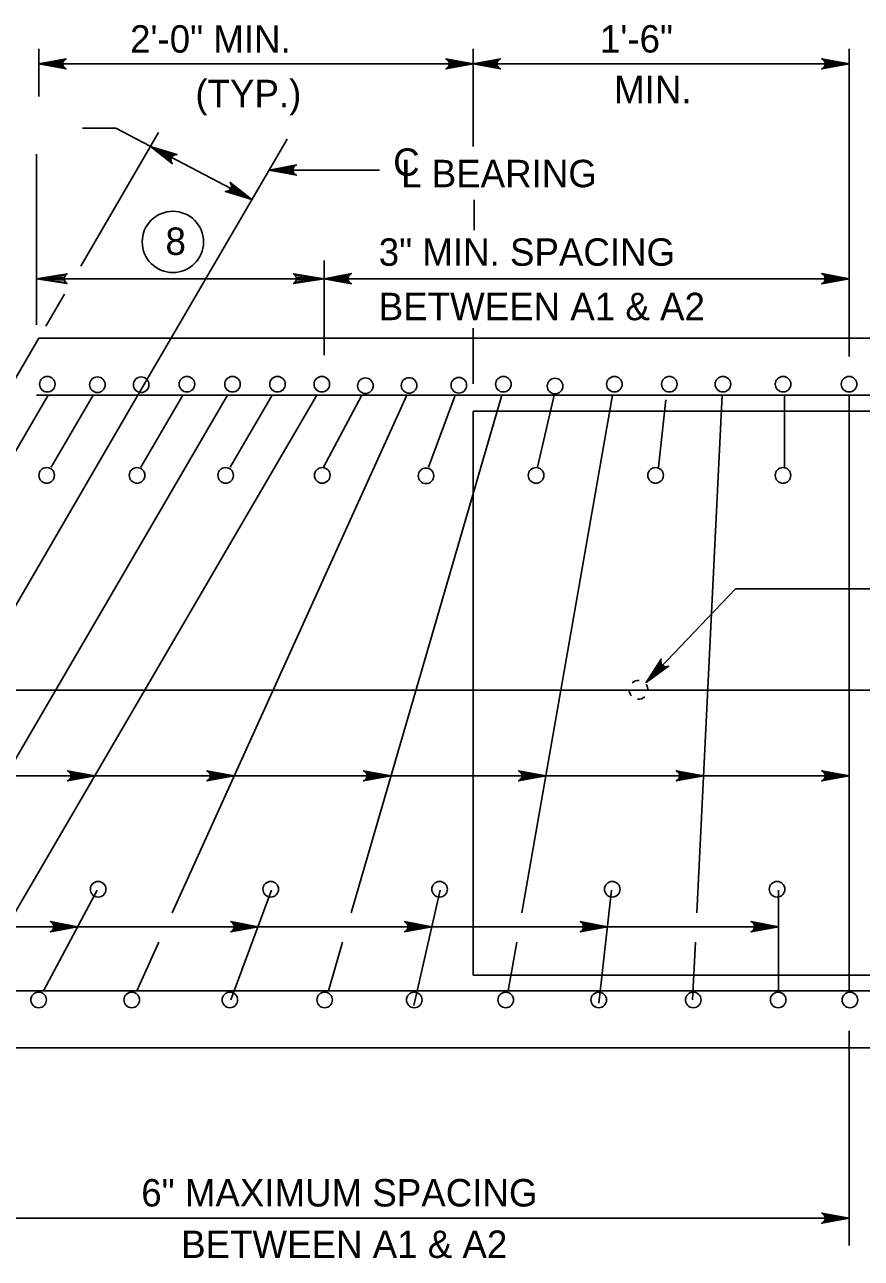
# Model space of a CAD drawing. Extents: x 639331 to 643089, y 299088 to 300975.
# Drawn here: x 641717.4 to 641808.9, y 299343 to 299477.9 of the extents above; entities that cross this region are included whole.
import ezdxf

# ---------------------------------------------------------------- set-up
doc = ezdxf.new("R2010")
doc.units = 0
doc.layers.add('1', color=7, linetype='Continuous')

msp = doc.modelspace()

# ---------------------------------------------------------------- linework, layer by layer
at = {"layer": '1'}
for p, q in [((641718.94, 299473.67), (641766.44, 299473.67)), ((641766.44, 299473.67), (641807.54, 299473.67)), ((641723.54, 299451.55), (641732.02, 299466.16)), ((641727.35, 299466.62), (641723.72, 299466.62)), ((641742.25, 299458.83), (641727.35, 299466.62)), ((641729.52, 299437), (641746.1, 299465.44)), ((641756.19, 299462.05), (641744.13, 299462.05)), ((641750.14, 299450.17), (641718.69, 299450.17)), ((641807.54, 299450.17), (641750.14, 299450.17)), ((641719.71, 299444.96), (641721.75, 299448.47)), ((641673.69, 299366.05), (641718.94, 299443.67)), ((641824.06, 299443.67), (641718.94, 299443.67)), ((641686.95, 299380.81), (641719.95, 299437.42)), ((641696.77, 299380.81), (641729.77, 299437.42)), ((641706.56, 299380.81), (641739.56, 299437.42)), ((641716.33, 299380.81), (641749.33, 299437.42)), ((641824.06, 299437.42), (641718.68, 299437.42)), ((641720.29, 299429.55), (641724.88, 299437.42)), ((641730.08, 299429.55), (641734.67, 299437.42)), ((641733.51, 299380.81), (641759.19, 299437.42)), ((641739.85, 299429.55), (641744.44, 299437.42)), ((641750.07, 299429.55), (641754.28, 299437.42)), ((641753.08, 299380.81), (641769.56, 299437.42)), ((641761.56, 299429.55), (641764.45, 299437.33)), ((641771.77, 299380.81), (641781.66, 299437.42)), ((641773.47, 299429.55), (641775.28, 299437.42)), ((641786.7, 299429.55), (641787.52, 299436.92)), ((641790.9, 299380.81), (641793.66, 299437.42)), ((641800.49, 299429.55), (641800.49, 299437.42)), ((641807.54, 299372.3), (641807.54, 299437.42)), ((641766.44, 299435.67), (641766.44, 299374)), ((641824.31, 299435.67), (641766.44, 299435.67)), ((641785.34, 299406.01), (641795.11, 299416.26)), ((641795.11, 299416.26), (641829.93, 299416.26)), ((641844.19, 299405.17), (641682.94, 299405.17)), ((641725.07, 299395.8), (641715.29, 299395.8)), ((641740.31, 299395.8), (641725.07, 299395.8)), ((641757.44, 299395.8), (641740.31, 299395.8)), ((641774.39, 299395.8), (641757.44, 299395.8)), ((641791.63, 299395.8), (641774.39, 299395.8)), ((641807.54, 299395.8), (641791.63, 299395.8)), ((641719.44, 299372.3), (641725.32, 299383.3)), ((641739.94, 299371.3), (641744.39, 299383.3)), ((641759.94, 299370.67), (641762.84, 299383.3)), ((641780.19, 299370.92), (641781.56, 299383.3)), ((641799.81, 299372.3), (641799.81, 299383.3)), ((641723.18, 299379.3), (641710.56, 299379.3)), ((641742.91, 299379.3), (641723.18, 299379.3)), ((641761.92, 299379.3), (641742.91, 299379.3)), ((641781.12, 299379.3), (641761.92, 299379.3)), ((641799.81, 299379.3), (641781.12, 299379.3)), ((641729.65, 299372.3), (641732.06, 299377.6)), ((641750.6, 299372.3), (641752.15, 299377.6)), ((641770.28, 299372.3), (641771.21, 299377.6)), ((641790.44, 299371.3), (641790.75, 299377.6)), ((641824.06, 299374), (641766.44, 299374)), ((641824.06, 299372.3), (641680.56, 299372.3)), ((641824.06, 299366.05), (641673.69, 299366.05)), ((641807.54, 299347.42), (641710.91, 299347.42)), ((641736.06, 299347.42), (641727.06, 299347.42))]:
    msp.add_line(p, q, dxfattribs=at)
for points in [[(641718.94, 299475.3), (641718.94, 299470.1)], [(641718.94, 299473.67), (641721.92, 299474.23), (641721.81, 299474.15), (641721.69, 299474.07), (641721.63, 299473.97), (641721.57, 299473.87), (641721.56, 299473.77), (641721.54, 299473.67), (641721.56, 299473.57), (641721.57, 299473.47), (641721.63, 299473.37), (641721.69, 299473.27), (641721.81, 299473.19), (641721.92, 299473.11), (641718.94, 299473.67), (641721.81, 299473.19), (641721.69, 299473.27), (641718.94, 299473.67), (641721.63, 299473.37), (641721.57, 299473.47), (641718.94, 299473.67), (641721.56, 299473.57), (641721.54, 299473.67), (641718.94, 299473.67), (641721.56, 299473.77), (641721.57, 299473.87), (641718.94, 299473.67), (641721.63, 299473.97), (641721.69, 299474.07), (641718.94, 299473.67), (641721.81, 299474.15)], [(641718.94, 299473.67), (641721.92, 299474.23), (641721.81, 299474.15), (641721.69, 299474.07), (641721.63, 299473.97), (641721.57, 299473.87), (641721.56, 299473.77), (641721.54, 299473.67), (641721.56, 299473.57), (641721.57, 299473.47), (641721.63, 299473.37), (641721.69, 299473.27), (641721.81, 299473.19), (641721.92, 299473.11), (641718.94, 299473.67), (641721.81, 299473.19), (641721.69, 299473.27), (641718.94, 299473.67), (641721.63, 299473.37), (641721.57, 299473.47), (641718.94, 299473.67), (641721.56, 299473.57), (641721.54, 299473.67), (641718.94, 299473.67), (641721.56, 299473.77), (641721.57, 299473.87), (641718.94, 299473.67), (641721.63, 299473.97), (641721.69, 299474.07), (641718.94, 299473.67), (641721.81, 299474.15)], [(641766.44, 299473.67), (641763.46, 299473.11), (641763.57, 299473.19), (641763.69, 299473.27), (641763.74, 299473.37), (641763.8, 299473.47), (641763.82, 299473.57), (641763.84, 299473.67), (641763.82, 299473.77), (641763.8, 299473.87), (641763.74, 299473.97), (641763.69, 299474.07), (641763.57, 299474.15), (641763.46, 299474.23), (641766.44, 299473.67), (641763.57, 299474.15), (641763.69, 299474.07), (641766.44, 299473.67), (641763.74, 299473.97), (641763.8, 299473.87), (641766.44, 299473.67), (641763.82, 299473.77), (641763.84, 299473.67), (641766.44, 299473.67), (641763.82, 299473.57), (641763.8, 299473.47), (641766.44, 299473.67), (641763.74, 299473.37), (641763.69, 299473.27), (641766.44, 299473.67), (641763.57, 299473.19)], [(641766.44, 299475.3), (641766.44, 299464.63)], [(641766.44, 299473.67), (641769.42, 299474.23), (641769.31, 299474.15), (641769.19, 299474.07), (641769.13, 299473.97), (641769.07, 299473.87), (641769.06, 299473.77), (641769.04, 299473.67), (641769.06, 299473.57), (641769.07, 299473.47), (641769.13, 299473.37), (641769.19, 299473.27), (641769.31, 299473.19), (641769.42, 299473.11), (641766.44, 299473.67), (641769.31, 299473.19), (641769.19, 299473.27), (641766.44, 299473.67), (641769.13, 299473.37), (641769.07, 299473.47), (641766.44, 299473.67), (641769.06, 299473.57), (641769.04, 299473.67), (641766.44, 299473.67), (641769.06, 299473.77), (641769.07, 299473.87), (641766.44, 299473.67), (641769.13, 299473.97), (641769.19, 299474.07), (641766.44, 299473.67), (641769.31, 299474.15)], [(641807.54, 299473.67), (641804.55, 299473.11), (641804.67, 299473.19), (641804.78, 299473.27), (641804.84, 299473.37), (641804.9, 299473.47), (641804.92, 299473.57), (641804.94, 299473.67), (641804.92, 299473.77), (641804.9, 299473.87), (641804.84, 299473.97), (641804.78, 299474.07), (641804.67, 299474.15), (641804.55, 299474.23), (641807.54, 299473.67), (641804.67, 299474.15), (641804.78, 299474.07), (641807.54, 299473.67), (641804.84, 299473.97), (641804.9, 299473.87), (641807.54, 299473.67), (641804.92, 299473.77), (641804.94, 299473.67), (641807.54, 299473.67), (641804.92, 299473.57), (641804.9, 299473.47), (641807.54, 299473.67), (641804.84, 299473.37), (641804.78, 299473.27), (641807.54, 299473.67), (641804.67, 299473.19)], [(641807.54, 299475.3), (641807.54, 299441.65)], [(641731.14, 299464.64), (641734.04, 299463.75), (641733.91, 299463.73), (641733.77, 299463.72), (641733.67, 299463.65), (641733.57, 299463.59), (641733.51, 299463.51), (641733.45, 299463.43), (641733.41, 299463.34), (641733.38, 299463.24), (641733.39, 299463.12), (641733.4, 299463.01), (641733.46, 299462.88), (641733.53, 299462.76), (641731.14, 299464.64), (641733.46, 299462.88), (641733.4, 299463.01), (641731.14, 299464.64), (641733.39, 299463.12), (641733.38, 299463.24), (641731.14, 299464.64), (641733.41, 299463.34), (641733.45, 299463.43), (641731.14, 299464.64), (641733.51, 299463.51), (641733.57, 299463.59), (641731.14, 299464.64), (641733.67, 299463.65), (641733.77, 299463.72), (641731.14, 299464.64), (641733.91, 299463.73)], [(641718.69, 299445.13), (641718.69, 299463.8)], [(641744.13, 299462.05), (641747.11, 299462.61), (641746.99, 299462.53), (641746.88, 299462.45), (641746.82, 299462.35), (641746.76, 299462.25), (641746.74, 299462.15), (641746.73, 299462.05), (641746.74, 299461.95), (641746.76, 299461.85), (641746.82, 299461.75), (641746.88, 299461.65), (641746.99, 299461.57), (641747.11, 299461.49), (641744.13, 299462.05), (641746.99, 299461.57), (641746.88, 299461.65), (641744.13, 299462.05), (641746.82, 299461.75), (641746.76, 299461.85), (641744.13, 299462.05), (641746.74, 299461.95), (641746.73, 299462.05), (641744.13, 299462.05), (641746.74, 299462.15), (641746.76, 299462.25), (641744.13, 299462.05), (641746.82, 299462.35), (641746.88, 299462.45), (641744.13, 299462.05), (641746.99, 299462.53)], [(641742.25, 299458.83), (641739.35, 299459.71), (641739.48, 299459.73), (641739.62, 299459.75), (641739.72, 299459.81), (641739.82, 299459.87), (641739.88, 299459.95), (641739.94, 299460.03), (641739.98, 299460.13), (641740.01, 299460.22), (641740, 299460.34), (641739.99, 299460.46), (641739.93, 299460.58), (641739.86, 299460.7), (641742.25, 299458.83), (641739.93, 299460.58), (641739.99, 299460.46), (641742.25, 299458.83), (641740, 299460.34), (641740.01, 299460.22), (641742.25, 299458.83), (641739.98, 299460.13), (641739.94, 299460.03), (641742.25, 299458.83), (641739.88, 299459.95), (641739.82, 299459.87), (641742.25, 299458.83), (641739.72, 299459.81), (641739.62, 299459.75), (641742.25, 299458.83), (641739.48, 299459.73)], [(641766.56, 299455.47), (641766.56, 299458.8)], [(641750.14, 299452.17), (641750.14, 299441.8)], [(641721.87, 299449.77), (641721.75, 299450), (641718.69, 299450.17), (641721.87, 299449.77), (641722.03, 299449.63), (641718.69, 299450.17), (641721.75, 299450.32), (641721.86, 299450.55), (641718.69, 299450.17), (641722.03, 299450.7), (641721.86, 299450.55)], [(641746.96, 299450.57), (641747.08, 299450.34), (641750.14, 299450.17), (641746.96, 299450.57), (641746.8, 299450.71), (641750.14, 299450.17), (641747.09, 299450.02), (641746.97, 299449.79), (641750.14, 299450.17), (641746.8, 299449.64), (641746.97, 299449.79)], [(641750.14, 299450.17), (641753.13, 299450.73), (641753.01, 299450.65), (641752.9, 299450.57), (641752.84, 299450.47), (641752.78, 299450.37), (641752.76, 299450.27), (641752.74, 299450.17), (641752.76, 299450.07), (641752.78, 299449.97), (641752.84, 299449.87), (641752.9, 299449.77), (641753.01, 299449.69), (641753.13, 299449.61), (641750.14, 299450.17), (641753.01, 299449.69), (641752.9, 299449.77), (641750.14, 299450.17), (641752.84, 299449.87), (641752.78, 299449.97), (641750.14, 299450.17), (641752.76, 299450.07), (641752.74, 299450.17), (641750.14, 299450.17), (641752.76, 299450.27), (641752.78, 299450.37), (641750.14, 299450.17), (641752.84, 299450.47), (641752.9, 299450.57), (641750.14, 299450.17), (641753.01, 299450.65)], [(641807.54, 299450.17), (641804.55, 299449.61), (641804.67, 299449.69), (641804.78, 299449.77), (641804.84, 299449.87), (641804.9, 299449.97), (641804.92, 299450.07), (641804.94, 299450.17), (641804.92, 299450.27), (641804.9, 299450.37), (641804.84, 299450.47), (641804.78, 299450.57), (641804.67, 299450.65), (641804.55, 299450.73), (641807.54, 299450.17), (641804.67, 299450.65), (641804.78, 299450.57), (641807.54, 299450.17), (641804.84, 299450.47), (641804.9, 299450.37), (641807.54, 299450.17), (641804.92, 299450.27), (641804.94, 299450.17), (641807.54, 299450.17), (641804.92, 299450.07), (641804.9, 299449.97), (641807.54, 299450.17), (641804.84, 299449.87), (641804.78, 299449.77), (641807.54, 299450.17), (641804.67, 299449.69)], [(641766.44, 299444.74), (641766.44, 299438.67)], [(641785.34, 299406.01), (641786.99, 299408.56), (641786.97, 299408.42), (641786.95, 299408.28), (641786.98, 299408.17), (641787.01, 299408.06), (641787.07, 299407.97), (641787.13, 299407.89), (641787.22, 299407.84), (641787.3, 299407.78), (641787.42, 299407.75), (641787.53, 299407.73), (641787.67, 299407.76), (641787.8, 299407.78), (641785.34, 299406.01), (641787.67, 299407.76), (641787.53, 299407.73), (641785.34, 299406.01), (641787.42, 299407.75), (641787.3, 299407.78), (641785.34, 299406.01), (641787.22, 299407.84), (641787.13, 299407.89), (641785.34, 299406.01), (641787.07, 299407.97), (641787.01, 299408.06), (641785.34, 299406.01), (641786.98, 299408.17), (641786.95, 299408.28), (641785.34, 299406.01), (641786.97, 299408.42)], [(641725.07, 299395.8), (641722.09, 299395.24), (641722.2, 299395.32), (641722.32, 299395.4), (641722.38, 299395.5), (641722.44, 299395.6), (641722.45, 299395.7), (641722.47, 299395.8), (641722.45, 299395.9), (641722.44, 299396), (641722.38, 299396.1), (641722.32, 299396.2), (641722.2, 299396.28), (641722.09, 299396.36), (641725.07, 299395.8), (641722.2, 299396.28), (641722.32, 299396.2), (641725.07, 299395.8), (641722.38, 299396.1), (641722.44, 299396), (641725.07, 299395.8), (641722.45, 299395.9), (641722.47, 299395.8), (641725.07, 299395.8), (641722.45, 299395.7), (641722.44, 299395.6), (641725.07, 299395.8), (641722.38, 299395.5), (641722.32, 299395.4), (641725.07, 299395.8), (641722.2, 299395.32)], [(641740.31, 299395.8), (641737.33, 299395.24), (641737.44, 299395.32), (641737.56, 299395.4), (641737.62, 299395.5), (641737.68, 299395.6), (641737.69, 299395.7), (641737.71, 299395.8), (641737.69, 299395.9), (641737.68, 299396), (641737.62, 299396.1), (641737.56, 299396.2), (641737.44, 299396.28), (641737.33, 299396.36), (641740.31, 299395.8), (641737.44, 299396.28), (641737.56, 299396.2), (641740.31, 299395.8), (641737.62, 299396.1), (641737.68, 299396), (641740.31, 299395.8), (641737.69, 299395.9), (641737.71, 299395.8), (641740.31, 299395.8), (641737.69, 299395.7), (641737.68, 299395.6), (641740.31, 299395.8), (641737.62, 299395.5), (641737.56, 299395.4), (641740.31, 299395.8), (641737.44, 299395.32)], [(641757.44, 299395.8), (641754.46, 299395.24), (641754.58, 299395.32), (641754.69, 299395.4), (641754.75, 299395.5), (641754.81, 299395.6), (641754.83, 299395.7), (641754.84, 299395.8), (641754.83, 299395.9), (641754.81, 299396), (641754.75, 299396.1), (641754.69, 299396.2), (641754.58, 299396.28), (641754.46, 299396.36), (641757.44, 299395.8), (641754.58, 299396.28), (641754.69, 299396.2), (641757.44, 299395.8), (641754.75, 299396.1), (641754.81, 299396), (641757.44, 299395.8), (641754.83, 299395.9), (641754.84, 299395.8), (641757.44, 299395.8), (641754.83, 299395.7), (641754.81, 299395.6), (641757.44, 299395.8), (641754.75, 299395.5), (641754.69, 299395.4), (641757.44, 299395.8), (641754.58, 299395.32)], [(641774.39, 299395.8), (641771.4, 299395.24), (641771.52, 299395.32), (641771.63, 299395.4), (641771.69, 299395.5), (641771.75, 299395.6), (641771.77, 299395.7), (641771.79, 299395.8), (641771.77, 299395.9), (641771.75, 299396), (641771.69, 299396.1), (641771.63, 299396.2), (641771.52, 299396.28), (641771.4, 299396.36), (641774.39, 299395.8), (641771.52, 299396.28), (641771.63, 299396.2), (641774.39, 299395.8), (641771.69, 299396.1), (641771.75, 299396), (641774.39, 299395.8), (641771.77, 299395.9), (641771.79, 299395.8), (641774.39, 299395.8), (641771.77, 299395.7), (641771.75, 299395.6), (641774.39, 299395.8), (641771.69, 299395.5), (641771.63, 299395.4), (641774.39, 299395.8), (641771.52, 299395.32)], [(641791.63, 299395.8), (641788.65, 299395.24), (641788.76, 299395.32), (641788.88, 299395.4), (641788.94, 299395.5), (641789, 299395.6), (641789.01, 299395.7), (641789.03, 299395.8), (641789.01, 299395.9), (641789, 299396), (641788.94, 299396.1), (641788.88, 299396.2), (641788.76, 299396.28), (641788.65, 299396.36), (641791.63, 299395.8), (641788.76, 299396.28), (641788.88, 299396.2), (641791.63, 299395.8), (641788.94, 299396.1), (641789, 299396), (641791.63, 299395.8), (641789.01, 299395.9), (641789.03, 299395.8), (641791.63, 299395.8), (641789.01, 299395.7), (641789, 299395.6), (641791.63, 299395.8), (641788.94, 299395.5), (641788.88, 299395.4), (641791.63, 299395.8), (641788.76, 299395.32)], [(641807.54, 299395.8), (641804.55, 299395.24), (641804.67, 299395.32), (641804.78, 299395.4), (641804.84, 299395.5), (641804.9, 299395.6), (641804.92, 299395.7), (641804.94, 299395.8), (641804.92, 299395.9), (641804.9, 299396), (641804.84, 299396.1), (641804.78, 299396.2), (641804.67, 299396.28), (641804.55, 299396.36), (641807.54, 299395.8), (641804.67, 299396.28), (641804.78, 299396.2), (641807.54, 299395.8), (641804.84, 299396.1), (641804.9, 299396), (641807.54, 299395.8), (641804.92, 299395.9), (641804.94, 299395.8), (641807.54, 299395.8), (641804.92, 299395.7), (641804.9, 299395.6), (641807.54, 299395.8), (641804.84, 299395.5), (641804.78, 299395.4), (641807.54, 299395.8), (641804.67, 299395.32)], [(641723.18, 299379.3), (641720.2, 299378.74), (641720.32, 299378.82), (641720.43, 299378.9), (641720.49, 299379), (641720.55, 299379.1), (641720.57, 299379.2), (641720.58, 299379.3), (641720.57, 299379.4), (641720.55, 299379.5), (641720.49, 299379.6), (641720.43, 299379.7), (641720.32, 299379.78), (641720.2, 299379.86), (641723.18, 299379.3), (641720.32, 299379.78), (641720.43, 299379.7), (641723.18, 299379.3), (641720.49, 299379.6), (641720.55, 299379.5), (641723.18, 299379.3), (641720.57, 299379.4), (641720.58, 299379.3), (641723.18, 299379.3), (641720.57, 299379.2), (641720.55, 299379.1), (641723.18, 299379.3), (641720.49, 299379), (641720.43, 299378.9), (641723.18, 299379.3), (641720.32, 299378.82)], [(641742.91, 299379.3), (641739.93, 299378.74), (641740.04, 299378.82), (641740.16, 299378.9), (641740.21, 299379), (641740.27, 299379.1), (641740.29, 299379.2), (641740.31, 299379.3), (641740.29, 299379.4), (641740.27, 299379.5), (641740.21, 299379.6), (641740.16, 299379.7), (641740.04, 299379.78), (641739.93, 299379.86), (641742.91, 299379.3), (641740.04, 299379.78), (641740.16, 299379.7), (641742.91, 299379.3), (641740.21, 299379.6), (641740.27, 299379.5), (641742.91, 299379.3), (641740.29, 299379.4), (641740.31, 299379.3), (641742.91, 299379.3), (641740.29, 299379.2), (641740.27, 299379.1), (641742.91, 299379.3), (641740.21, 299379), (641740.16, 299378.9), (641742.91, 299379.3), (641740.04, 299378.82)], [(641761.92, 299379.3), (641758.94, 299378.74), (641759.05, 299378.82), (641759.17, 299378.9), (641759.23, 299379), (641759.29, 299379.1), (641759.3, 299379.2), (641759.32, 299379.3), (641759.3, 299379.4), (641759.29, 299379.5), (641759.23, 299379.6), (641759.17, 299379.7), (641759.05, 299379.78), (641758.94, 299379.86), (641761.92, 299379.3), (641759.05, 299379.78), (641759.17, 299379.7), (641761.92, 299379.3), (641759.23, 299379.6), (641759.29, 299379.5), (641761.92, 299379.3), (641759.3, 299379.4), (641759.32, 299379.3), (641761.92, 299379.3), (641759.3, 299379.2), (641759.29, 299379.1), (641761.92, 299379.3), (641759.23, 299379), (641759.17, 299378.9), (641761.92, 299379.3), (641759.05, 299378.82)], [(641781.12, 299379.3), (641778.14, 299378.74), (641778.25, 299378.82), (641778.37, 299378.9), (641778.42, 299379), (641778.48, 299379.1), (641778.5, 299379.2), (641778.52, 299379.3), (641778.5, 299379.4), (641778.48, 299379.5), (641778.42, 299379.6), (641778.37, 299379.7), (641778.25, 299379.78), (641778.14, 299379.86), (641781.12, 299379.3), (641778.25, 299379.78), (641778.37, 299379.7), (641781.12, 299379.3), (641778.42, 299379.6), (641778.48, 299379.5), (641781.12, 299379.3), (641778.5, 299379.4), (641778.52, 299379.3), (641781.12, 299379.3), (641778.5, 299379.2), (641778.48, 299379.1), (641781.12, 299379.3), (641778.42, 299379), (641778.37, 299378.9), (641781.12, 299379.3), (641778.25, 299378.82)], [(641799.81, 299379.3), (641796.83, 299378.74), (641796.95, 299378.82), (641797.06, 299378.9), (641797.12, 299379), (641797.18, 299379.1), (641797.2, 299379.2), (641797.21, 299379.3), (641797.2, 299379.4), (641797.18, 299379.5), (641797.12, 299379.6), (641797.06, 299379.7), (641796.95, 299379.78), (641796.83, 299379.86), (641799.81, 299379.3), (641796.95, 299379.78), (641797.06, 299379.7), (641799.81, 299379.3), (641797.12, 299379.6), (641797.18, 299379.5), (641799.81, 299379.3), (641797.2, 299379.4), (641797.21, 299379.3), (641799.81, 299379.3), (641797.2, 299379.2), (641797.18, 299379.1), (641799.81, 299379.3), (641797.12, 299379), (641797.06, 299378.9), (641799.81, 299379.3), (641796.95, 299378.82)], [(641807.54, 299367.92), (641807.54, 299344.42)], [(641807.54, 299347.42), (641804.55, 299346.86), (641804.67, 299346.94), (641804.78, 299347.02), (641804.84, 299347.12), (641804.9, 299347.22), (641804.92, 299347.32), (641804.94, 299347.42), (641804.92, 299347.52), (641804.9, 299347.62), (641804.84, 299347.72), (641804.78, 299347.82), (641804.67, 299347.9), (641804.55, 299347.98), (641807.54, 299347.42), (641804.67, 299347.9), (641804.78, 299347.82), (641807.54, 299347.42), (641804.84, 299347.72), (641804.9, 299347.62), (641807.54, 299347.42), (641804.92, 299347.52), (641804.94, 299347.42), (641807.54, 299347.42), (641804.92, 299347.32), (641804.9, 299347.22), (641807.54, 299347.42), (641804.84, 299347.12), (641804.78, 299347.02), (641807.54, 299347.42), (641804.67, 299346.94)]]:
    msp.add_lwpolyline(points, dxfattribs=at)
for centre, radius in [((641733.6, 299454.19), 3.35), ((641719.87, 299438.63), 0.853), ((641725.35, 299438.57), 0.853), ((641730.13, 299438.57), 0.853), ((641735.14, 299438.63), 0.853), ((641740.12, 299438.63), 0.853), ((641745.04, 299438.63), 0.853), ((641749.89, 299438.63), 0.853), ((641754.65, 299438.46), 0.853), ((641759.43, 299438.49), 0.853), ((641764.87, 299438.52), 0.853), ((641769.74, 299438.63), 0.853), ((641775.39, 299438.42), 0.853), ((641781.88, 299438.63), 0.853), ((641787.89, 299438.63), 0.853), ((641793.75, 299438.63), 0.853), ((641800.33, 299438.63), 0.853), ((641807.55, 299438.63), 0.853), ((641719.8, 299428.66), 0.853), ((641729.68, 299428.66), 0.853), ((641739.37, 299428.66), 0.853), ((641749.93, 299428.66), 0.853), ((641761.28, 299428.61), 0.853), ((641773.32, 299428.66), 0.853), ((641786.39, 299428.66), 0.853), ((641800.32, 299428.66), 0.853), ((641725.43, 299383.39), 0.853), ((641744.3, 299383.39), 0.853), ((641762.77, 299383.39), 0.853), ((641781.65, 299383.39), 0.853), ((641799.67, 299383.39), 0.853), ((641718.92, 299371.29), 0.853), ((641729.1, 299371.29), 0.853), ((641739.83, 299371.29), 0.853), ((641750.2, 299371.29), 0.853), ((641760, 299371.29), 0.853), ((641770, 299371.29), 0.853), ((641780.17, 299371.29), 0.853), ((641790.51, 299371.29), 0.853), ((641799.79, 299371.29), 0.853), ((641807.64, 299371.29), 0.853)]:
    msp.add_circle(centre, radius, dxfattribs=at)
for start, end in [(86.0742, 133.7618), (354.4991, 34.5723), (180, 219.8329), (264.1454, 311.4426)]:
    msp.add_arc((641784.52, 299405.21), 1.03, start, end, dxfattribs=at)

# ---------------------------------------------------------------- texts
for s, p in [('2\'-0" MIN.', (641728.92, 299474.89)), ('1\'-6"', (641780.3, 299474.9)), ('(TYP.)', (641736.06, 299468.92)), ('MIN.', (641781.85, 299469.36)), ('C', (641757.69, 299461.42)), ('L BEARING', (641758.56, 299460.17)), ('8', (641732.79, 299452.77)), ('3" MIN. SPACING', (641756.11, 299451.58)), ('BETWEEN A1 & A2', (641756.11, 299445.63)), ('6" MAXIMUM SPACING', (641730.14, 299348.7)), ('BETWEEN A1 & A2', (641734.5, 299343.07))]:
    msp.add_text(s, height=3, rotation=360, dxfattribs=at).set_placement(p)

doc.saveas('drawing.dxf')
